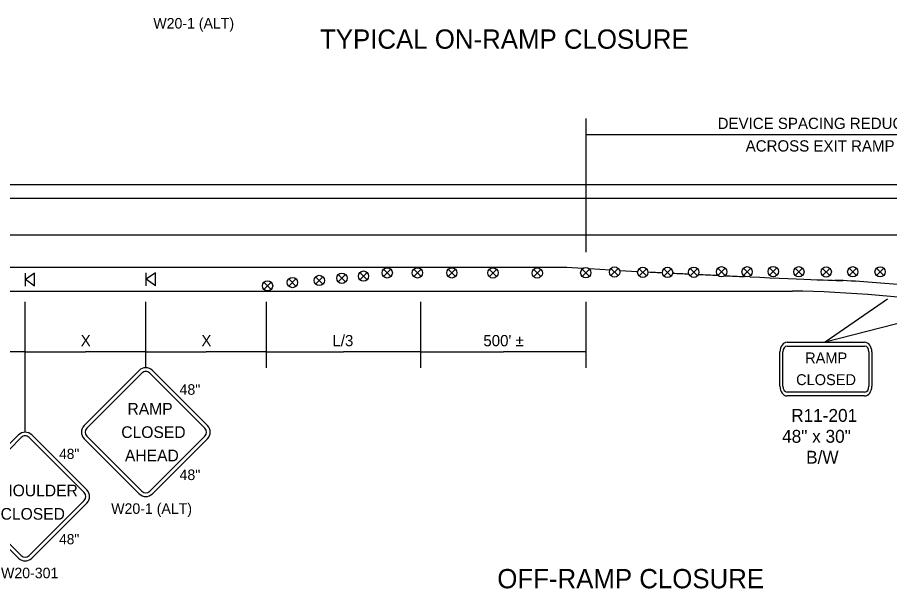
# Model space of a CAD drawing. Extents: x 99988 to 100172, y 99995 to 100047.
# Drawn here: x 100006.52 to 100011.94, y 100002.7 to 100006.25 of the extents above; entities that cross this region are included whole.
import ezdxf

# ---------------------------------------------------------------- set-up
doc = ezdxf.new("R2010")
doc.units = 0
for name, color, linetype in [('Default', 7, 'Continuous'), ('Level 15', 7, 'Continuous'), ('Level 20', 7, 'Continuous'), ('SH_DE_DetailBody1Text', 7, 'Continuous'), ('SH_DE_DetailHeading2Text', 7, 'Continuous'), ('TR_SN_RegulatorySigns', 7, 'Continuous'), ('TR_SN_WarningSigns', 7, 'Continuous'), ('TR_WZ_WorkZoneDetails', 7, 'Continuous')]:
    doc.layers.add(name, color=color, linetype=linetype)

# ---------------------------------------------------------------- blocks, each defined once
blk = doc.blocks.new('W20-301')
at = {"layer": 'TR_SN_WarningSigns'}
for p, q in [((-0.5113, 0.6882), (-0.0544, 1.1451)), ((-0.4895, 0.6665), (-0.0326, 1.1234)), ((0.0327, 1.1234), (0.4896, 0.6665)), ((0.0544, 1.1451), (0.5113, 0.6882)), ((-0.0544, 0.1225), (-0.5113, 0.5794)), ((-0.0326, 0.1443), (-0.4895, 0.6012)), ((0.4896, 0.6012), (0.0327, 0.1443)), ((0.5113, 0.5794), (0.0544, 0.1225))]:
    blk.add_line(p, q, dxfattribs=at)
for centre, radius, start, end in [((0, 1.0907), 0.0769, 44.99628, 134.99965), ((0, 1.0907), 0.0462, 44.99628, 134.99965), ((-0.4569, 0.6338), 0.0769, 134.99657, 224.99357), ((-0.4569, 0.6338), 0.0462, 134.99657, 224.99357), ((0.4569, 0.6338), 0.0462, 314.99936, 44.99485), ((0.4569, 0.6338), 0.0769, 314.99936, 44.99485), ((0, 0.1769), 0.0769, 225, 314.99958), ((0, 0.1769), 0.0462, 225, 314.99958)]:
    blk.add_arc(centre, radius, start, end, dxfattribs=at)
for s, height, p in [('48"', 0.0848, (0.2818, 0.945)), ('SHOULDER', 0.09691, (-0.2836, 0.6358)), ('CLOSED', 0.09691, (-0.2033, 0.4419)), ('48"', 0.0848, (0.2818, 0.2379)), ('W20-301', 0.0875, (-0.1999, -0.0438))]:
    blk.add_text(s, height=height, dxfattribs=at).set_placement(p)

msp = doc.modelspace()

# ---------------------------------------------------------------- linework, layer by layer
at = {"layer": 'Default'}
for p, q in [((100004.2658, 100004.8971), (100015.1319, 100004.8971)), ((100008.6948, 100004.6172), (100008.6495, 100004.6625)), ((100008.6948, 100004.6625), (100008.6495, 100004.6172)), ((100008.8421, 100004.6374), (100008.7969, 100004.6826)), ((100008.8421, 100004.6826), (100008.7969, 100004.6374)), ((100009.0297, 100004.6374), (100008.9844, 100004.6826)), ((100009.0297, 100004.6826), (100008.9844, 100004.6374)), ((100009.2441, 100004.6374), (100009.1988, 100004.6826)), ((100009.2441, 100004.6826), (100009.1988, 100004.6374)), ((100009.4997, 100004.6368), (100009.4545, 100004.682)), ((100009.4997, 100004.682), (100009.4545, 100004.6368)), ((100009.7753, 100004.6366), (100009.73, 100004.6818)), ((100009.7753, 100004.6818), (100009.73, 100004.6366)), ((100009.937, 100004.6961), (100010.0375, 100004.6899)), ((100010.0766, 100004.6384), (100010.0313, 100004.6837)), ((100010.0766, 100004.6837), (100010.0313, 100004.6384)), ((100010.0768, 100004.6874), (100010.2048, 100004.6795)), ((100010.2558, 100004.6428), (100010.2105, 100004.688)), ((100010.2558, 100004.688), (100010.2105, 100004.6428)), ((100010.2658, 100004.6757), (100010.3745, 100004.669)), ((100010.431, 100004.6407), (100010.3858, 100004.686)), ((100010.431, 100004.686), (100010.3858, 100004.6407)), ((100010.5848, 100004.6405), (100010.5395, 100004.6857)), ((100010.5848, 100004.6857), (100010.5395, 100004.6405)), ((100010.7475, 100004.6411), (100010.7022, 100004.6864)), ((100010.7475, 100004.6864), (100010.7022, 100004.6411)), ((100010.9208, 100004.6441), (100010.8755, 100004.6893)), ((100010.9208, 100004.6893), (100010.8755, 100004.6441)), ((100011.0796, 100004.6441), (100011.0344, 100004.6893)), ((100011.0796, 100004.6893), (100011.0344, 100004.6441)), ((100011.2422, 100004.6452), (100011.197, 100004.6904)), ((100011.2422, 100004.6904), (100011.197, 100004.6452)), ((100011.4012, 100004.6441), (100011.3559, 100004.6893)), ((100011.4012, 100004.6893), (100011.3559, 100004.6441)), ((100011.5711, 100004.6429), (100011.5259, 100004.6882)), ((100011.5711, 100004.6882), (100011.5259, 100004.6429)), ((100011.7361, 100004.6441), (100011.6909, 100004.6893)), ((100011.7361, 100004.6893), (100011.6909, 100004.6441)), ((100011.9064, 100004.6438), (100011.8611, 100004.689)), ((100011.9064, 100004.689), (100011.8611, 100004.6438)), ((100006.6278, 100004.6587), (100006.5701, 100004.6184)), ((100006.5701, 100004.5783), (100006.5701, 100004.6587)), ((100006.6278, 100004.5783), (100006.5701, 100004.6184)), ((100006.6278, 100004.5783), (100006.6278, 100004.6587)), ((100007.3796, 100004.6609), (100007.3219, 100004.6206)), ((100007.3219, 100004.5804), (100007.3219, 100004.6609)), ((100007.3796, 100004.5804), (100007.3219, 100004.6206)), ((100007.3796, 100004.5804), (100007.3796, 100004.6609)), ((100008.2526, 100004.577), (100008.2074, 100004.6223)), ((100008.2526, 100004.6223), (100008.2074, 100004.577)), ((100008.4201, 100004.5904), (100008.3748, 100004.6357)), ((100008.4201, 100004.6357), (100008.3748, 100004.5904)), ((100008.5608, 100004.6038), (100008.5155, 100004.6491)), ((100008.5608, 100004.6491), (100008.5155, 100004.6038)), ((100008.0985, 100004.5569), (100008.0533, 100004.6021)), ((100008.0985, 100004.6021), (100008.0533, 100004.5569))]:
    msp.add_line(p, q, dxfattribs=at)
for centre in [(100008.6721, 100004.6399), (100008.8195, 100004.66), (100009.0071, 100004.66), (100009.2214, 100004.66), (100009.4771, 100004.6594), (100009.7526, 100004.6592), (100010.054, 100004.661), (100010.2331, 100004.6654), (100010.4084, 100004.6633), (100010.5621, 100004.6631), (100010.7248, 100004.6638), (100010.8982, 100004.6667), (100011.057, 100004.6667), (100011.2196, 100004.6678), (100011.3785, 100004.6667), (100011.5485, 100004.6656), (100011.7135, 100004.6667), (100011.8837, 100004.6664), (100008.0759, 100004.5795), (100008.23, 100004.5996), (100008.3975, 100004.613), (100008.5381, 100004.6265)]:
    msp.add_circle(centre, 0.032, dxfattribs=at)
at = {"layer": 'Level 15'}
for p, q in [((100010.0571, 100005.5197), (100012.0375, 100005.5197)), ((100006.569, 100004.1687), (100006.194, 100004.1687)), ((100006.569, 100004.1687), (100006.944, 100004.1687)), ((100007.319, 100004.1687), (100006.944, 100004.1687)), ((100007.319, 100004.1687), (100007.694, 100004.1687)), ((100008.069, 100004.1687), (100007.694, 100004.1687)), ((100008.069, 100004.1687), (100008.5488, 100004.1687)), ((100009.0286, 100004.1687), (100008.5488, 100004.1687)), ((100009.0286, 100004.1687), (100009.5429, 100004.1687)), ((100010.0571, 100004.1687), (100009.5429, 100004.1687))]:
    msp.add_line(p, q, dxfattribs=at)
at = {"layer": 'TR_SN_RegulatorySigns'}
for points in [[(100011.3053, 100004.2284), (100011.7875, 100004.2284)], [(100011.3053, 100004.2046), (100011.7875, 100004.2046)], [(100011.2607, 100003.9546), (100011.2607, 100004.1689)], [(100011.2786, 100003.9546), (100011.2786, 100004.1689)], [(100011.8143, 100004.1689), (100011.8143, 100003.9546)], [(100011.8322, 100004.1689), (100011.8322, 100003.9546)], [(100011.7875, 100003.9189), (100011.3053, 100003.9189)], [(100011.7875, 100003.8951), (100011.3053, 100003.8951)]]:
    msp.add_lwpolyline(points, dxfattribs=at)
for centre, major_axis, start_param, end_param in [((100011.3053, 100004.1689), (0, -0.0595), 3.141593, 4.712389), ((100011.7875, 100004.1689), (0, 0.0595), 4.712389, 6.283185), ((100011.3053, 100004.1689), (0, -0.0357), 3.141593, 4.712389), ((100011.7875, 100004.1689), (0, 0.0357), 4.712389, 6.283185), ((100011.3053, 100003.9546), (0, -0.0595), 4.712389, 6.283185), ((100011.3053, 100003.9546), (0, -0.0357), 4.712389, 6.283185), ((100011.7875, 100003.9546), (0, 0.0357), 3.141593, 4.712389), ((100011.7875, 100003.9546), (0, 0.0595), 3.141593, 4.712389)]:
    msp.add_ellipse(centre, major_axis=major_axis, ratio=0.75, start_param=start_param, end_param=end_param, dxfattribs=at)
at = {"layer": 'TR_SN_WarningSigns'}
for p, q in [((100006.9355, 100003.7103), (100007.2782, 100004.053)), ((100006.9519, 100003.694), (100007.2945, 100004.0367)), ((100007.3435, 100004.0367), (100007.6862, 100003.694)), ((100007.3598, 100004.053), (100007.7025, 100003.7103)), ((100007.2945, 100003.3024), (100006.9519, 100003.645)), ((100007.6862, 100003.645), (100007.3435, 100003.3024)), ((100007.2782, 100003.2861), (100006.9355, 100003.6287)), ((100007.7025, 100003.6287), (100007.3598, 100003.2861))]:
    msp.add_line(p, q, dxfattribs=at)
for centre, radius, start, end in [((100007.319, 100004.0122), 0.0577, 44.9963, 134.9997), ((100007.319, 100004.0122), 0.0346, 44.9963, 134.9997), ((100006.9763, 100003.6695), 0.0577, 134.9966, 224.9936), ((100006.9763, 100003.6695), 0.0346, 134.9966, 224.9936), ((100007.6617, 100003.6695), 0.0346, 314.9994, 44.9948), ((100007.6617, 100003.6695), 0.0577, 314.9994, 44.9948), ((100007.319, 100003.3269), 0.0577, 225, 314.9996), ((100007.319, 100003.3269), 0.0346, 225, 314.9996)]:
    msp.add_arc(centre, radius, start, end, dxfattribs=at)
at = {"layer": 'TR_WZ_WorkZoneDetails'}
for p, q in [((100010.0571, 100004.7882), (100010.0571, 100005.6197)), ((100004.2658, 100005.2089), (100015.1308, 100005.2089)), ((100004.2658, 100005.1256), (100015.1308, 100005.1256)), ((100004.2658, 100004.6961), (100009.937, 100004.6961)), ((100005.0504, 100004.5463), (100011.3395, 100004.5463)), ((100009.9389, 100004.5463), (100011.3395, 100004.5463)), ((100012.743, 100004.5355), (100011.5426, 100004.2296)), ((100006.569, 100003.6694), (100006.569, 100004.4804)), ((100007.319, 100004.0699), (100007.319, 100004.4804)), ((100008.069, 100004.0687), (100008.069, 100004.4804)), ((100009.0286, 100004.0687), (100009.0286, 100004.4804)), ((100010.0571, 100004.0687), (100010.0571, 100004.4804)), ((100011.9293, 100004.4973), (100011.5426, 100004.2296))]:
    msp.add_line(p, q, dxfattribs=at)
for centre, major_axis, ratio, start_param, end_param in [((100010.7956, 100004.6537), (0.8567, -0.0405), 0.006094, 4.287755, 4.401293), ((100010.7956, 100004.6537), (0.8567, -0.0405), 0.006094, 4.476809, 4.59455), ((100010.7956, 100004.6537), (0.8567, -0.0405), 0.006094, 4.663656, 4.803284), ((100010.7956, 100004.6537), (0.8567, -0.0405), 0.006094, 4.8588, 5.001535), ((100010.7956, 100004.6537), (0.8567, -0.0405), 0.006094, 5.042848, 6.283185), ((100012.4018, 100004.1565), (-1.9237, 0.2704), 0.196247, 4.939264, 5.168134), ((100012.3573, 100004.0823), (-1.9237, 0.2704), 0.196247, 4.089543, 5.297244)]:
    msp.add_ellipse(centre, major_axis=major_axis, ratio=ratio, start_param=start_param, end_param=end_param, dxfattribs=at)

# ---------------------------------------------------------------- block references
at = {"layer": 'TR_WZ_WorkZoneDetails', "xscale": 0.7500000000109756, "yscale": 0.7500000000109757}
msp.add_blockref('W20-301', (100006.569, 100002.7937), dxfattribs=at)

# ---------------------------------------------------------------- texts
at = {"layer": 'Level 20'}
for s, p in [('DEVICE SPACING REDUCED TO 1/2 DISTANCE', (100010.8734, 100005.5547)), ('X', (100006.9143, 100004.2037))]:
    msp.add_text(s, height=0.07, rotation=360, dxfattribs=at).set_placement(p)
for s, p in [('ACROSS EXIT RAMP DURING CLOSURE', (100011.0477, 100005.4147)), ('X', (100007.6643, 100004.2037)), ('L/3', (100008.4788, 100004.2037)), ("500' ± ", (100009.4172, 100004.2037))]:
    msp.add_text(s, height=0.07, dxfattribs=at).set_placement(p)
at = {"layer": 'SH_DE_DetailBody1Text'}
for s, p in [('R11-201', (100011.3306, 100003.7336)), ('48" x 30"', (100011.2744, 100003.6036)), ('B/W', (100011.4235, 100003.4736))]:
    msp.add_text(s, height=0.08, dxfattribs=at).set_placement(p)
at = {"layer": 'SH_DE_DetailHeading2Text'}
for s, p in [('TYPICAL ON-RAMP CLOSURE', (100008.402, 100006.0538)), (' OFF-RAMP CLOSURE', (100009.4594, 100002.6985))]:
    msp.add_text(s, height=0.12, dxfattribs=at).set_placement(p)
at = {"layer": 'TR_SN_RegulatorySigns'}
for s, p in [('RAMP', (100011.4176, 100004.0973)), ('CLOSED', (100011.3614, 100003.962))]:
    msp.add_text(s, height=0.06769, dxfattribs=at).set_placement(p)
at = {"layer": 'TR_SN_WarningSigns'}
for s, height, p in [('W20-1 (ALT)', 0.065625, (100007.3658, 100006.1794)), ('48"', 0.06563, (100007.5287, 100003.9019)), ('RAMP', 0.07268, (100007.205, 100003.7786)), ('CLOSED', 0.07268, (100007.1665, 100003.6332)), ('AHEAD', 0.07268, (100007.1893, 100003.4878)), ('48"', 0.06563, (100007.5287, 100003.3715)), ('W20-1 (ALT)', 0.065625, (100007.1039, 100003.1613))]:
    msp.add_text(s, height=height, dxfattribs=at).set_placement(p)

doc.saveas('drawing.dxf')
